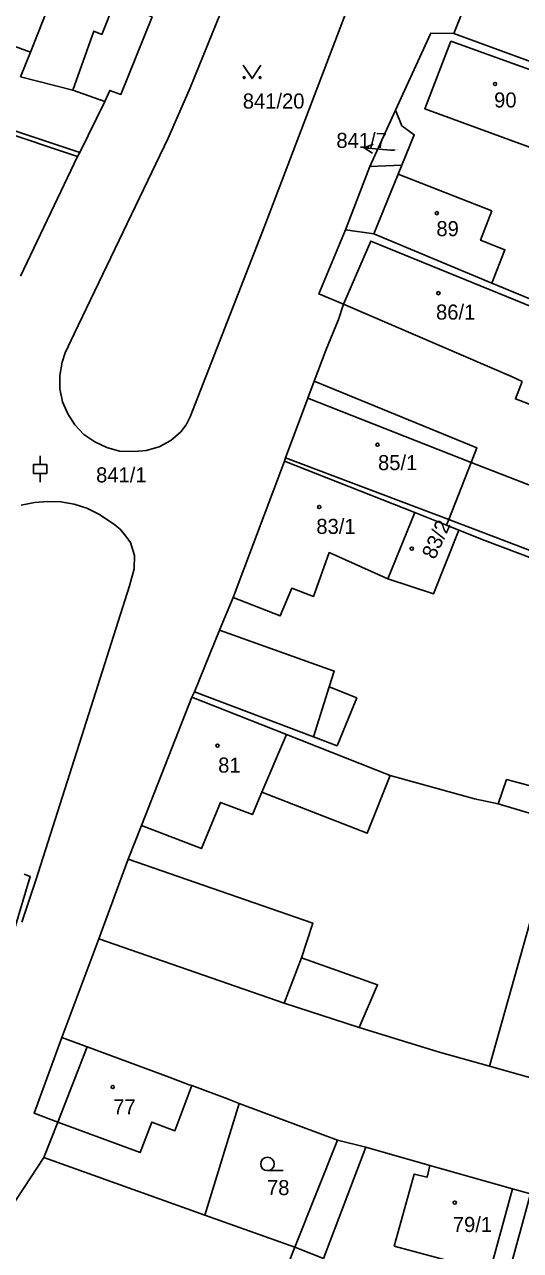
# Model space of a CAD drawing. Extents: x -737240 to -735272, y -1119606 to -1117878.
# Drawn here: x -736982.1 to -736926.2, y -1119123.6 to -1118985.3 of the extents above; entities that cross this region are included whole.
import ezdxf

# ---------------------------------------------------------------- set-up
doc = ezdxf.new("R2010")
doc.units = 0
for name, color, linetype in [('Level 1', 7, 'Continuous'), ('Level 16', 7, 'Continuous'), ('Level 18', 7, 'Continuous'), ('Level 19', 7, 'Continuous'), ('Level 25', 7, 'Continuous'), ('Level 4', 7, 'Continuous')]:
    doc.layers.add(name, color=color, linetype=linetype)

msp = doc.modelspace()

# ---------------------------------------------------------------- linework, layer by layer
at = {"layer": 'Level 1'}
for p, q in [((-736933.67, -1118986.3), (-736929.58, -1118976)), ((-736933.67, -1118986.3), (-736918.3, -1118991.95)), ((-736973.03, -1118993.99), (-736975.83, -1118999.73)), ((-736990.13, -1118995.5), (-736976.1, -1119000.18)), ((-736943.16, -1119001.33), (-736940.24, -1118994.96)), ((-736976.1, -1119000.18), (-736982.52, -1119013.7)), ((-736975.83, -1118999.73), (-736976.1, -1119000.18)), ((-736945.89, -1119008.47), (-736943.16, -1119001.33)), ((-736943.16, -1119001.33), (-736939.52, -1119001.18)), ((-736939.52, -1119001.18), (-736939.96, -1119002.19)), ((-736945.89, -1119008.47), (-736942.69, -1119008.91)), ((-736942.69, -1119008.91), (-736929.4, -1119014.47)), ((-736929.4, -1119014.47), (-736925.09, -1119016.25)), ((-736950.12, -1119027.43), (-736949.41, -1119025.51)), ((-736952.64, -1119034.16), (-736950.12, -1119027.43)), ((-736958.57, -1119049.91), (-736952.78, -1119034.53)), ((-736952.78, -1119034.53), (-736952.64, -1119034.16)), ((-736952.78, -1119034.53), (-736938.09, -1119040.35)), ((-736931.71, -1119034.68), (-736934.25, -1119041.14)), ((-736938.09, -1119040.35), (-736941.12, -1119047.81)), ((-736938.09, -1119040.35), (-736934.5, -1119041.77)), ((-736934.25, -1119041.14), (-736934.5, -1119041.77)), ((-736934.5, -1119041.77), (-736933.12, -1119042.32)), ((-736960.1, -1119053.62), (-736958.57, -1119049.91)), ((-736962.92, -1119060.57), (-736960.1, -1119053.62)), ((-736968.88, -1119075.62), (-736963.22, -1119061.17)), ((-736963.22, -1119061.17), (-736962.92, -1119060.57)), ((-736963.22, -1119061.17), (-736952.54, -1119065.39)), ((-736952.54, -1119065.39), (-736940.87, -1119070.01)), ((-736928.66, -1119073.19), (-736921.92, -1119075.23)), ((-736970.4, -1119079.42), (-736968.88, -1119075.62)), ((-736922.84, -1119078.51), (-736929.66, -1119102.79)), ((-736973.72, -1119088.42), (-736970.4, -1119079.42)), ((-736977.87, -1119099.53), (-736973.72, -1119088.42)), ((-736952.79, -1119095.66), (-736973.72, -1119088.42)), ((-736944.34, -1119098.42), (-736952.79, -1119095.66)), ((-736977.87, -1119099.53), (-736975.03, -1119100.58)), ((-736921.23, -1119105.15), (-736929.66, -1119102.79)), ((-736957.87, -1119106.97), (-736961.76, -1119119.57)), ((-736957.87, -1119106.97), (-736946.8, -1119111.11)), ((-736979.91, -1119113.09), (-736978.33, -1119109.11)), ((-736946.8, -1119111.11), (-736951.6, -1119123.2)), ((-736946.8, -1119111.11), (-736943.58, -1119111.91)), ((-736943.58, -1119111.91), (-736936.37, -1119113.96)), ((-736979.91, -1119113.09), (-736986.62, -1119123.28)), ((-736961.76, -1119119.57), (-736979.91, -1119113.09)), ((-736936.37, -1119113.96), (-736927.06, -1119116.6)), ((-736925.04, -1119117.17), (-736927.6, -1119126.54)), ((-736927.06, -1119116.6), (-736925.04, -1119117.17)), ((-736951.6, -1119123.2), (-736961.76, -1119119.57)), ((-736948.37, -1119124.45), (-736951.6, -1119123.2))]:
    msp.add_line(p, q, dxfattribs=at)
for points in [[(-736944.51, -1118980.43), (-736954.99, -1119007.98), (-736963.39, -1119029.54), (-736963.85, -1119030.44), (-736964.44, -1119031.25), (-736965.57, -1119032.23), (-736966.91, -1119032.94), (-736968.35, -1119033.33), (-736969.63, -1119033.47), (-736971.36, -1119033.43), (-736972.81, -1119033), (-736974.14, -1119032.37), (-736975.38, -1119031.55), (-736976.39, -1119030.44), (-736977.21, -1119029.21), (-736977.78, -1119027.84), (-736978.1, -1119026.39), (-736978.1, -1119024.9), (-736977.85, -1119023.38), (-736977.5, -1119022.31), (-736976.48, -1119020.18), (-736965.9, -1118998.13), (-736963.41, -1118992.46)], [(-736963.41, -1118992.46), (-736959.48, -1118982.81)], [(-736967.69, -1118984.44), (-736971.21, -1118993.18), (-736972.46, -1118992.74), (-736973.03, -1118993.99)], [(-736940.24, -1118994.96), (-736936.26, -1118986.26), (-736933.67, -1118986.3)], [(-736939.52, -1119001.18), (-736938.13, -1118997.73), (-736939.53, -1118996.72), (-736940.24, -1118994.96)], [(-736939.96, -1119002.19), (-736929.39, -1119006.33), (-736930.65, -1119009.64), (-736927.91, -1119010.73), (-736929.4, -1119014.47)], [(-736946.1, -1119016.84), (-736948.9, -1119015.68), (-736945.89, -1119008.47)], [(-736949.41, -1119025.51), (-736948.08, -1119021.96), (-736946.68, -1119018.57), (-736946.1, -1119016.84)], [(-736949.41, -1119025.51), (-736931.07, -1119033.04), (-736931.71, -1119034.68)], [(-736982.45, -1119039.52), (-736980.97, -1119039.22), (-736979.46, -1119039.1), (-736977.97, -1119039.13), (-736976.49, -1119039.38), (-736975.06, -1119039.85), (-736973.72, -1119040.52), (-736972.04, -1119041.63), (-736971.28, -1119042.23), (-736970.64, -1119042.99), (-736970.13, -1119043.72), (-736969.67, -1119045.17), (-736969.7, -1119046.69), (-736970.23, -1119048.6), (-736975.08, -1119063.87), (-736980.8, -1119081.8), (-736982.4, -1119086.54)], [(-736941.12, -1119047.81), (-736935.96, -1119049.5), (-736933.12, -1119042.32)], [(-736933.12, -1119042.32), (-736930.19, -1119043.48), (-736920.83, -1119047.01)], [(-736940.87, -1119070.01), (-736931.34, -1119072.63), (-736928.66, -1119073.19)], [(-736982.12, -1119081.12), (-736981.43, -1119081.39), (-736983.2, -1119087.34), (-736984.19, -1119087.05)], [(-736929.66, -1119102.79), (-736935.43, -1119101.17), (-736944.34, -1119098.42)], [(-736978.33, -1119109.11), (-736981.01, -1119108.08), (-736977.87, -1119099.53)], [(-736975.03, -1119100.58), (-736965.76, -1119104.03), (-736963.51, -1119104.87), (-736963.23, -1119104.97)], [(-736963.23, -1119104.97), (-736959.19, -1119106.47), (-736957.87, -1119106.97)], [(-736942.74, -1119138.48), (-736954.91, -1119131.54), (-736951.6, -1119123.2)]]:
    msp.add_lwpolyline(points, dxfattribs=at)
at = {"layer": 'Level 16'}
for points in [[(-736942.833, -1118999.801), (-736943.791, -1118999.223), (-736942.754, -1118998.804)], [(-736940.38, -1118999.49), (-736940.8, -1118999.46), (-736943.791, -1118999.223)]]:
    msp.add_lwpolyline(points, dxfattribs=at)
at = {"layer": 'Level 25'}
for p, q in [((-736980.32, -1119034.93), (-736980.32, -1119033.93)), ((-736980.32, -1119035.93), (-736980.32, -1119036.93)), ((-736952.908, -1119114.56), (-736954.69, -1119114.56))]:
    msp.add_line(p, q, dxfattribs=at)
msp.add_lwpolyline([(-736955.42, -1118989.89), (-736956.42, -1118991.39), (-736957.42, -1118989.89)], dxfattribs=at)
msp.add_lwpolyline([(-736981.07, -1119035.93), (-736979.57, -1119035.93), (-736979.57, -1119034.93), (-736981.07, -1119034.93)], close=True, dxfattribs=at)
for centre in [(-736957.32, -1118991.29), (-736955.52, -1118991.29)]:
    msp.add_circle(centre, 0.1, dxfattribs=at)
for centre, major_axis, ratio in [((-736929.03, -1118992.01), (0.18, 0), 0.9848078), ((-736935.59, -1119006.58), (0.18, 0), 0.9848078), ((-736935.41, -1119015.6), (0.18, 0), 0.9848078), ((-736942.28, -1119032.69), (0.18, 0), 0.9848078), ((-736948.85, -1119039.72), (0.18, 0), 0.9848078), ((-736938.42, -1119044.41), (0.18, 0), 0.9848078), ((-736960.32, -1119066.63), (0.18, 0), 0.9848078), ((-736972.14, -1119105.13), (0.18, 0), 0.9848078), ((-736954.69, -1119113.804), (0.764, 0), 0.9894236), ((-736933.57, -1119118.16), (0.18, 0), 0.9848078)]:
    msp.add_ellipse(centre, major_axis=major_axis, ratio=ratio, dxfattribs=at)
at = {"layer": 'Level 4'}
for p, q in [((-736987.26, -1118986.29), (-736981.42, -1118988.42)), ((-736981.42, -1118988.42), (-736982.52, -1118991.21)), ((-736982.52, -1118991.21), (-736976.65, -1118992.71)), ((-736976.65, -1118992.71), (-736973.03, -1118993.99)), ((-736975.83, -1118999.73), (-736989.98, -1118995.02)), ((-736939.96, -1119002.19), (-736942.69, -1119008.91)), ((-736950.12, -1119027.43), (-736931.71, -1119034.68)), ((-736934.25, -1119041.14), (-736952.64, -1119034.16)), ((-736918.65, -1119039.81), (-736931.71, -1119034.68)), ((-736920.62, -1119046.31), (-736934.25, -1119041.14)), ((-736949.48, -1119065.64), (-736962.92, -1119060.57)), ((-736947.72, -1119060.01), (-736949.48, -1119065.64)), ((-736955.31, -1119071.87), (-736952.54, -1119065.39)), ((-736950.84, -1119090.57), (-736952.79, -1119095.66)), ((-736975.03, -1119100.58), (-736978.33, -1119109.11)), ((-736948.37, -1119124.45), (-736943.58, -1119111.91))]:
    msp.add_line(p, q, dxfattribs=at)
for points in [[(-736981.42, -1118988.42), (-736976.99, -1118977.19), (-736966.48, -1118981.36)], [(-736976.65, -1118992.71), (-736974.28, -1118986.04), (-736973.35, -1118986.41), (-736971.9, -1118982.76), (-736967.69, -1118984.44)], [(-736923.91, -1118999.59), (-736936.96, -1118994.81), (-736934.01, -1118987.18), (-736920.96, -1118991.88)], [(-736946.1, -1119016.84), (-736927.18, -1119024.98), (-736925.98, -1119025.58), (-736926.73, -1119027.52), (-736923.13, -1119028.92), (-736919.62, -1119019.75), (-736919.44, -1119019.31), (-736923.87, -1119017.55), (-736943.03, -1119009.73), (-736946.1, -1119016.84)], [(-736958.57, -1119049.91), (-736953.25, -1119051.99), (-736951.95, -1119048.88), (-736949.51, -1119049.79), (-736947.72, -1119044.85), (-736941.12, -1119047.81)], [(-736960.1, -1119053.62), (-736947.16, -1119058.22), (-736947.72, -1119060.01)], [(-736947.72, -1119060.01), (-736944.62, -1119061.25), (-736946.84, -1119066.64), (-736949.48, -1119065.64)], [(-736955.31, -1119071.87), (-736943.46, -1119076.5), (-736940.87, -1119070.01)], [(-736928.66, -1119073.19), (-736927.73, -1119070.46), (-736921.07, -1119072.21)], [(-736968.88, -1119075.62), (-736962.12, -1119078.23), (-736960, -1119073.03), (-736956.39, -1119074.4), (-736955.31, -1119071.87)], [(-736970.4, -1119079.42), (-736949.56, -1119086.65), (-736950.84, -1119090.57)], [(-736950.84, -1119090.57), (-736942.27, -1119093.6), (-736944.34, -1119098.42)], [(-736978.33, -1119109.11), (-736969.05, -1119112.52), (-736967.72, -1119109.09), (-736965.12, -1119110.06), (-736963.23, -1119104.97)], [(-736936.37, -1119113.96), (-736936.69, -1119115.3), (-736938.14, -1119114.95), (-736940.39, -1119123.09), (-736929.62, -1119125.97), (-736927.06, -1119116.6)]]:
    msp.add_lwpolyline(points, dxfattribs=at)

# ---------------------------------------------------------------- texts
at = {"layer": 'Level 16'}
msp.add_text('841/7', height=1.7, dxfattribs=at).set_placement((-736946.915, -1118999.22))
at = {"layer": 'Level 18'}
for s, height, p in [('841/20', 1.7, (-736957.47, -1118994.78)), ('841/7', 0.1, (-736940.38, -1118999.49)), ('841/1', 1.7, (-736974.01, -1119036.94)), ('78', 1.7, (-736954.74, -1119117.32))]:
    msp.add_text(s, height=height, dxfattribs=at).set_placement(p)
at = {"layer": 'Level 19'}
for s, p in [('90', (-736929.13, -1118994.66)), ('89', (-736935.64, -1119009.17)), ('86/1', (-736935.68, -1119018.58)), ('85/1', (-736942.22, -1119035.56)), ('83/1', (-736949.175, -1119042.75)), ('81', (-736960.245, -1119069.67)), ('77', (-736972.08, -1119108.22)), ('79/1', (-736933.785, -1119121.48))]:
    msp.add_text(s, height=1.7, dxfattribs=at).set_placement(p)
msp.add_text('83/2', height=1.7, rotation=65.67093, dxfattribs=at).set_placement((-736935.81, -1119045.72))

doc.saveas('drawing.dxf')
